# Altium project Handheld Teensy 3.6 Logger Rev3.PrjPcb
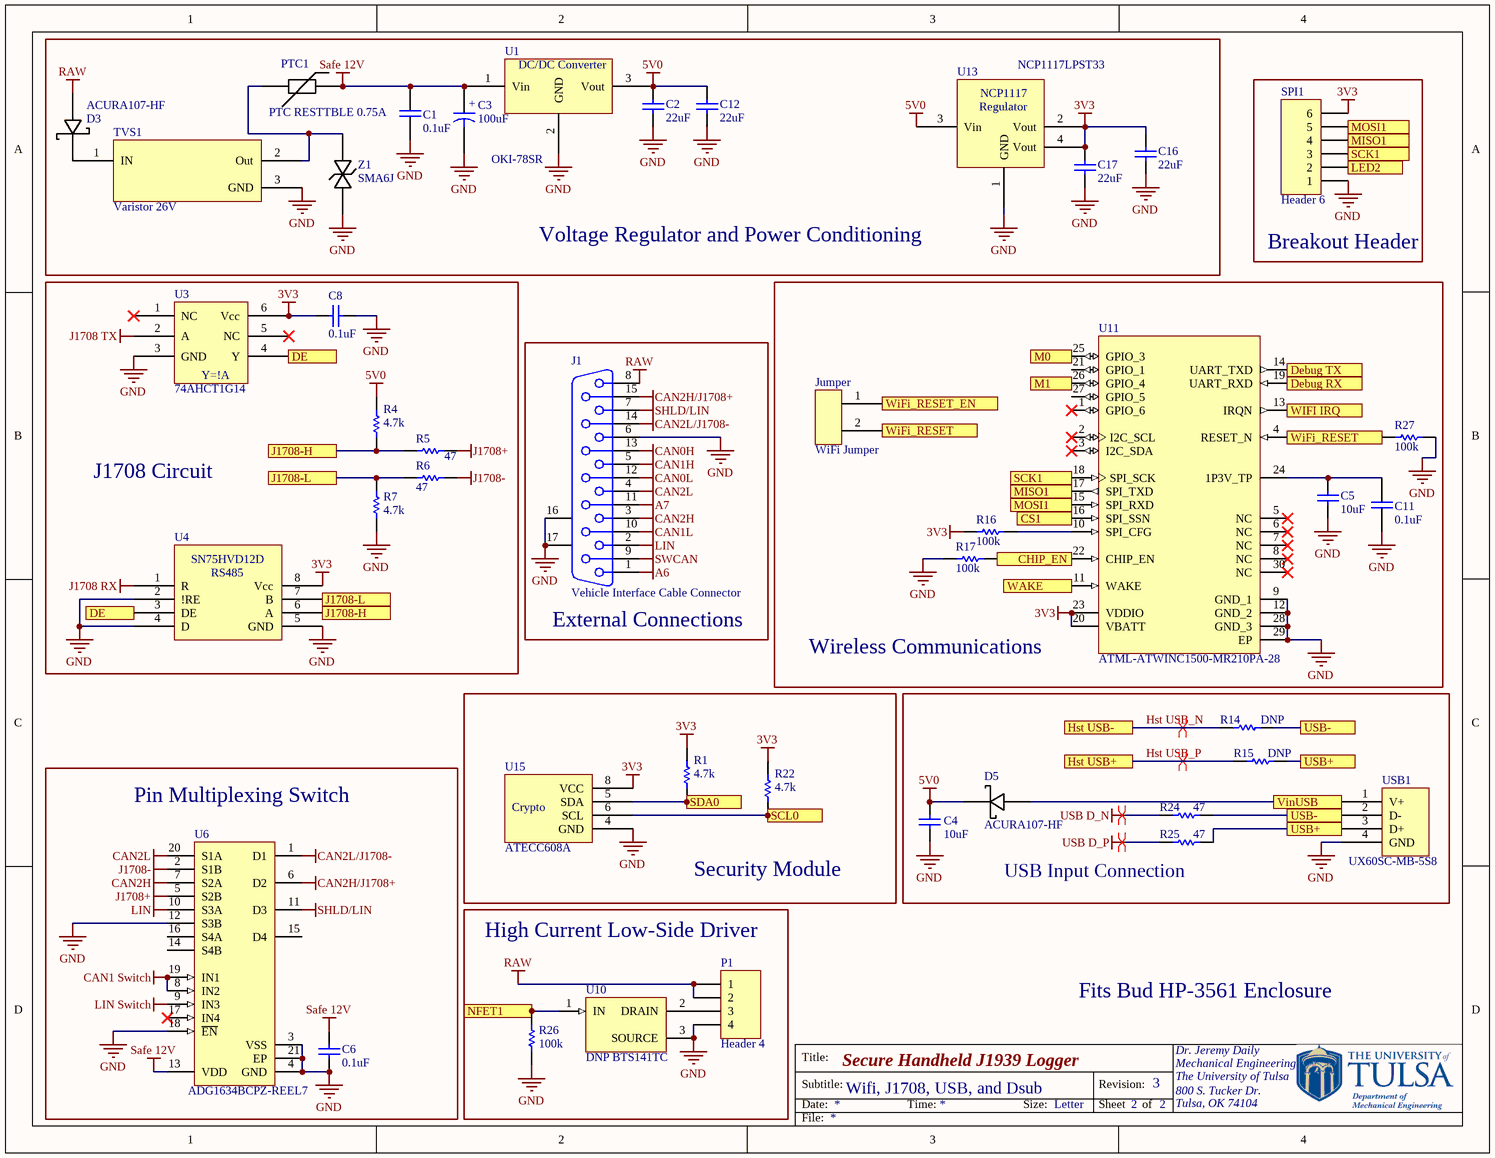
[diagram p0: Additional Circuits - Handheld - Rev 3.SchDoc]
2 sheets, 84 parts. Net scope: flat (ports and power ports of the same name join across sheets).
Board file: HP3561 PCB.PcbDoc
Sheets:
  Additional Circuits - Handheld - Rev 3.SchDoc
  Teensy 3.6 with J1939 - Handheld Rev3.SchDoc

## Sheet Additional Circuits - Handheld - Rev 3.SchDoc: Secure Handheld J1939 Logger
size Letter; Author: Dr. Jeremy Daily; CompanyName: The University of Tulsa; Organization: Mechanical Engineering; Address1: 800 S. Tucker Dr.; Address2: Tulsa, OK 74104; DocumentNumber: Wifi, J1708, USB, and Dsub; Revision: 3; SheetNumber: 2; SheetTotal: 2

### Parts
C1  0.1uF  [0603]
C2  22uF  [1206]
C3  100uF  [Elec. Cap - G]
C4  10uF  [0603]
C5  10uF  [0603]
C6  0.1uF  [0603]
C8  0.1uF  [0603]
C11  0.1uF  [0603]
C12  22uF  [1206]
C16  22uF  [1206]
C17  22uF  [1206]
D3  ACURA107-HF  [SMA with A and K]
D5  ACURA107-HF  [SMA with A and K]
J1  Vehicle Interface Cable Connector  [DSUB1.385-2H15]
Jumper  WiFi Jumper  [WiFi Jumper]
P1  Header 4  [HDR1X4]
PTC1  PTC RESTTBLE 0.75A  [1812]
R1  4.7k  [0603]
R4  4.7k  [0603]
R5  47  [0603]
R6  47  [0603]
R7  4.7k  [0603]
R14  DNP  [0603]
R15  DNP  [0603]
R16  100k  [0603]
R17  100k  [0603]
R22  4.7k  [0603]
R24  47  [0603]
R25  47  [0603]
R26  100k  [0603]
R27  100k  [0603]
SPI1  Header 6  [HDR1X6]
TVS1  Varistor 26V  [Transfeed]
U1  OKI-78SR  [OKI-78SR]
U3  74AHCT1G14  [SOT-353]
U4  SN75HVD08DR  [SOIC-SN8_N]  (value not drawn)
U6  ADG1634BCPZ-REEL7  [ADI-CP-20-4_N]
U10  DNP BTS141TC  [INF-PG-TO263-3-2_N]
U11  ATML-ATWINC1500-MR210PA-28  [ATML-ATWINC1500-MR210PA-28_V]
U13  NCP1117LPST33  [SOT-223]
U15  ATECC608A  [SOIC-8]
USB1  UX60SC-MB-5S8  [USB Mini UX60S]
Z1  SMA6J  [SMA]

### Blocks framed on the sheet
Voltage Regulator and Power Conditioning: C1-C3 C12 C16 C17 D3 PTC1 TVS1 U1 U13 Z1
Breakout Header: SPI1
J1708 Circuit: C8 R4-R7 U3 U4
Wireless Communications: C5 C11 Jumper R16 R17 R27 U11
External Connections: J1
Security Module: R1 R22 U15
USB Input Connection: C4 D5 R14 R15 R24 R25 USB1
Pin Multiplexing Switch: C6 U6
High Current Low-Side Driver: P1 R26 U10

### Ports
CHIP_EN, CS1, DE, Debug RX, Debug TX, Hst USB+, Hst USB-, J1708-H, J1708-L, LED2, M0, M1, MISO1, MOSI1, NFET1, SCK1, SCL0, SDA0, USB+, USB-, VinUSB, WAKE, WIFI IRQ, WiFi_RESET, WiFi_RESET_EN

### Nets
3V3: C8.2 C16.2 C17.2 R1.1 R16.2 R22.1 SPI1.6 U3.6(Vcc) U4.8(Vcc) U11.20(VBATT) U11.23(VDDIO) U13.2(Vout) U13.4(Vout) U15.8(VCC)
5V0: C2.2 C4.1 C12.2 D5.2(K) R4.1 U1.3(Vout) U13.3(Vin)
A6: J1.1
A7: J1.11
CAN0H: J1.13
CAN0L: J1.12
CAN1 Switch: U6.8(IN2) U6.19(IN1)
CAN1H: J1.5
CAN1L: J1.10
CAN2H: J1.3 U6.7(S2A)
CAN2H/J1708+: J1.15 U6.6(D2)
CAN2L: J1.4 U6.20(S1A)
CAN2L/J1708-: J1.14 U6.1(D1)
GND: C1.1 C2.1 C3.2(-) C4.2 C5.1 C6.1 C8.1 C11.1 C12.1 C16.1 C17.1 J1.6 J1.16(MH1) J1.17(MH2) P1.4 R7.2 R17.2 R26.2 R27.1 SPI1.1 TVS1.3(GND) U1.2(GND) U3.3(GND) U4.2(!RE) U4.4(D) U4.5(GND) U6.3(VSS) U6.4(GND) U6.12(S3B) U6.18(~{EN}) U6.21(EP) U10.3(SOURCE) U11.9(GND_1) U11.12(GND_2) U11.28(GND_3) U11.29(EP) U13.1(GND) U15.4(GND) USB1.4(GND) Z1.1(A)
J1708 RX: U4.1(R)
J1708 TX: U3.2(A)
J1708+: R5.2 U6.5(S2B)
J1708-: R6.2 U6.2(S1B)
LIN: J1.2 U6.10(S3A)
LIN Switch: U6.9(IN3)
RAW: D3.1(A) J1.8 P1.1 P1.2
Safe 12V: C1.2 C3.1 C6.2 PTC1.2 U1.1(Vin) U6.13(VDD)
SHLD/LIN: J1.7 U6.11(D3)
SWCAN: J1.9
USB D_N: R24.1
USB D_P: R25.1
Hst USB_N: R14.1 ; port Hst USB-
Hst USB_P: R15.1 ; port Hst USB+
NetC5_2: C5.2 C11.2 U11.24(1P3V_TP)
NetD2_1: SPI1.2 ; port LED2
NetD3_2: D3.2(K) TVS1.1(IN)
NetD5_1: D5.1(A) USB1.1(V+) ; port VinUSB
NetI2C_2: R22.2 U15.6(SCL) ; port SCL0
NetI2C_3: R1.2 U15.5(SDA) ; port SDA0
NetJumper_1: Jumper.1 ; port WiFi_RESET_EN
NetJumper_2: Jumper.2 R27.2 U11.4(RESET_N) ; port WiFi_RESET
NetP1_3: P1.3 U10.2(DRAIN)
NetPTC1_1: PTC1.1 TVS1.2(Out) Z1.2(K)
NetR4_2: R4.2 R5.1 U4.6(A) ; port J1708-H
NetR6_1: R6.1 R7.1 U4.7(B) ; port J1708-L
NetR14_2: R14.2 R24.2 USB1.2(D-) ; port USB-
NetR15_2: R15.2 R25.2 USB1.3(D+) ; port USB+
NetR16_1: R16.1 U11.10(SPI_CFG)
NetR17_1: R17.1 U11.22(CHIP_EN) ; port CHIP_EN
NetR26_1: R26.1 U10.1(IN) ; port NFET1
NetSPI1_3: SPI1.3 U11.18(SPI_SCK) ; port SCK1
NetSPI1_4: SPI1.4 U11.17(SPI_TXD) ; port MISO1
NetSPI1_5: SPI1.5 U11.15(SPI_RXD) ; port MOSI1
NetTeensy_3.6_30: U11.13(IRQN) ; port WIFI IRQ
NetTeensy_3.6_45: U11.16(SPI_SSN) ; port CS1
NetTeensy_3.6_63: U11.11(WAKE) ; port WAKE
NetTeensy_3.6_72: U11.19(UART_RXD) ; port Debug RX
NetTeensy_3.6_74: U11.14(UART_TXD) ; port Debug TX
NetU2_2: U11.25(GPIO_3) ; port M0
NetU2_3: U11.26(GPIO_4) ; port M1
NetU3_4: U3.4(Y) U4.3(DE) ; port DE

Not connected (* = marked no-connect by the designer): U3 1(NC)* 5(NC)*; U6 14(S4B) 15(D4) 16(S4A) 17(IN4)*; U11 1(GPIO_6)* 2(I2C_SCL)* 3(I2C_SDA)* 5(NC)* 6(NC)* 7(NC)* 8(NC)* 21(GPIO_1) 27(GPIO_5) 30(NC)*

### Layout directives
differential pair: Hst USB_N, Hst USB_P, USB D_N, USB D_P

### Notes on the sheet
- Fits Bud HP-3561 Enclosure

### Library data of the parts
C1 C11 = Cap: CAP CER 0.1UF 50V X7R 0603; Manufacturer: KEMET; PartNumber: C0603C104K5RACAUTO
C2 C12 C16 C17 = Cap: 22µF ±20% 25V Ceramic Capacitor X5R 1206 (3216 Metric); Manufacturer: Murata Electronics North America; PartNumber: GRT31CR61E226ME01L
C3 = Tantalum Cap_1: Aluminum Electrolytic Capacitors Radial, Can - SMD 5000 Hrs @ 105°C; Manufacturer: Panasonic Electronic Components; PartNumber: EEE-HC1H101P
C4 C5 = Cap: 10µF ±20% 25V Ceramic Capacitor X5R 0603 (1608 Metric); Manufacturer: Murata Electronics North America; PartNumber: ZRB18AR61E106ME01L
C6 C8 = Cap: CAP CER 0.1UF 50V 10% X7R 0603; Manufacturer: KEMET; PartNumber: C0603C104K5RACAUTO
D3 D5 = Schottky Diode: Diode Schottky 1000V 1A Surface Mount DO-214AC (SMA); Manufacturer: Comchip Technology
J1 = D Connector 15: Receptacle Assembly, 15 Position, Right Angle; Manufacturer: Amphenol FCI; PartNumber: D15S33E4GV00LF
P1 = Header 4: Header, 4-Pin
PTC1 = PTC: PTC RESTTBLE 0.75A 33V CHIP 1812; Manufacturer: Bel Fuse Inc.; PartNumber: 0ZCG0075BF2B
R1 R4 R7 R22 = Chip Resistor: ±1% 0.1W, 1/10W Chip Resistor 0603 (1608 Metric) Automotive AEC-Q200, High Voltage Thick Film; Manufacturer: Rohm Semiconductor; PartNumber: KTR03EZPF4701
R5 R6 R24 R25 = Chip Resistor: ±1% 0.1W, 1/10W Chip Resistor 0603 (1608 Metric) Automotive AEC-Q200, High Voltage Thick Film; Manufacturer: Rohm Semiconductor; PartNumber: KTR03EZPF47R0
R14 R15 = Chip Resistor: RES SMD 47 OHM 1% 1/10W 0603; Manufacturer: Panasonic Electronic Components; PartNumber: ERJ-3EKF47R0V
R16 R17 R26 R27 = Chip Resistor: ±1% 0.1W, 1/10W Chip Resistor 0603 (1608 Metric) Automotive AEC-Q200, High Voltage Thick Film; Manufacturer: Rohm Semiconductor; PartNumber: KTR03EZPF1003
SPI1 = Header 6: Header, 6-Pin
TVS1 = Transfeed: 34.5V 80A Varistor 1 Circuit Surface Mount 0805 (2012 Metric); Manufacturer: AVX; PartNumber: V2AF126C600Y2EDP
U1 = 7805: 5V DC/DC Converter (7805 replacement); Manufacturer: Murata Power Solutions Inc.; PartNumber: OKI-78SR-5/1.5-W36H-C
U3 = 74AHCT1G14 Inverter: IC SCHMIT-TRIGG INV GATE SOT353; Manufacturer: Diodes Incorporated; PartNumber: 74AHCT1G14SE-7
U4 = SN75HVD12D (3.3v RS485): IC RS485 TXRX 3/5V 8-SOIC; Manufacturer: Texas Instruments
U6 = ADG1634BCPZ-REEL7: IC SWITCH QUAD SPDT 20LFCSP; Manufacturer: Analog Devices
U10 = BTS141TC: Smart Low-Side Power Switch HITFET, 60 V VDS, 12 A ID, -40 to 150 degC, PG-TO263-3-2, Reel, Green; Manufacturer: Infineon; PartNumber: BTS141TCBUMA1
U11 = ATML-ATWINC1500-MR210PA-28: SMARTCONNECT ATWINC1500B-MU-T MO; Manufacturer: Microchip Technologies; PartNumber: ATWINC1510-MR210PB1140
U13 = NCP1117 2.5V: Linear Voltage Regulator IC Positive Fixed Output 3.3V 1A SOT-223; Manufacturer: On Semiconductor; PartNumber: NCP1117LPST33T3G
U15 = ATECC508A: Authentication Chip IC Networking and Communications 8-SOIC; Manufacturer: Microchip Technology; PartNumber: ATECC608A-SSHCZ-T
USB1 = USB-Rugged: USB - mini B USB 2.0 Receptacle Connector 5 Position Surface Mount, Right Angle; Through Hole; Manufacturer: Hirose
Z1 = Zener - Bidirectional: TVS DIODE 20VWM 36.8VC SMA; Manufacturer: Micro Commercial Co; PartNumber: SMA6J24CA-TP

## Sheet Teensy 3.6 with J1939 - Handheld Rev3.SchDoc: Secure Handheld J1939 Logger
size Letter; Author: Dr. Jeremy Daily; CompanyName: The University of Tulsa; Organization: Mechanical Engineering; Address1: 800 S. Tucker Dr.; Address2: Tulsa, OK 74104; DocumentNumber: Hands-On Heavy Duty Networking; Revision: 3; SheetNumber: 1; SheetTotal: 2
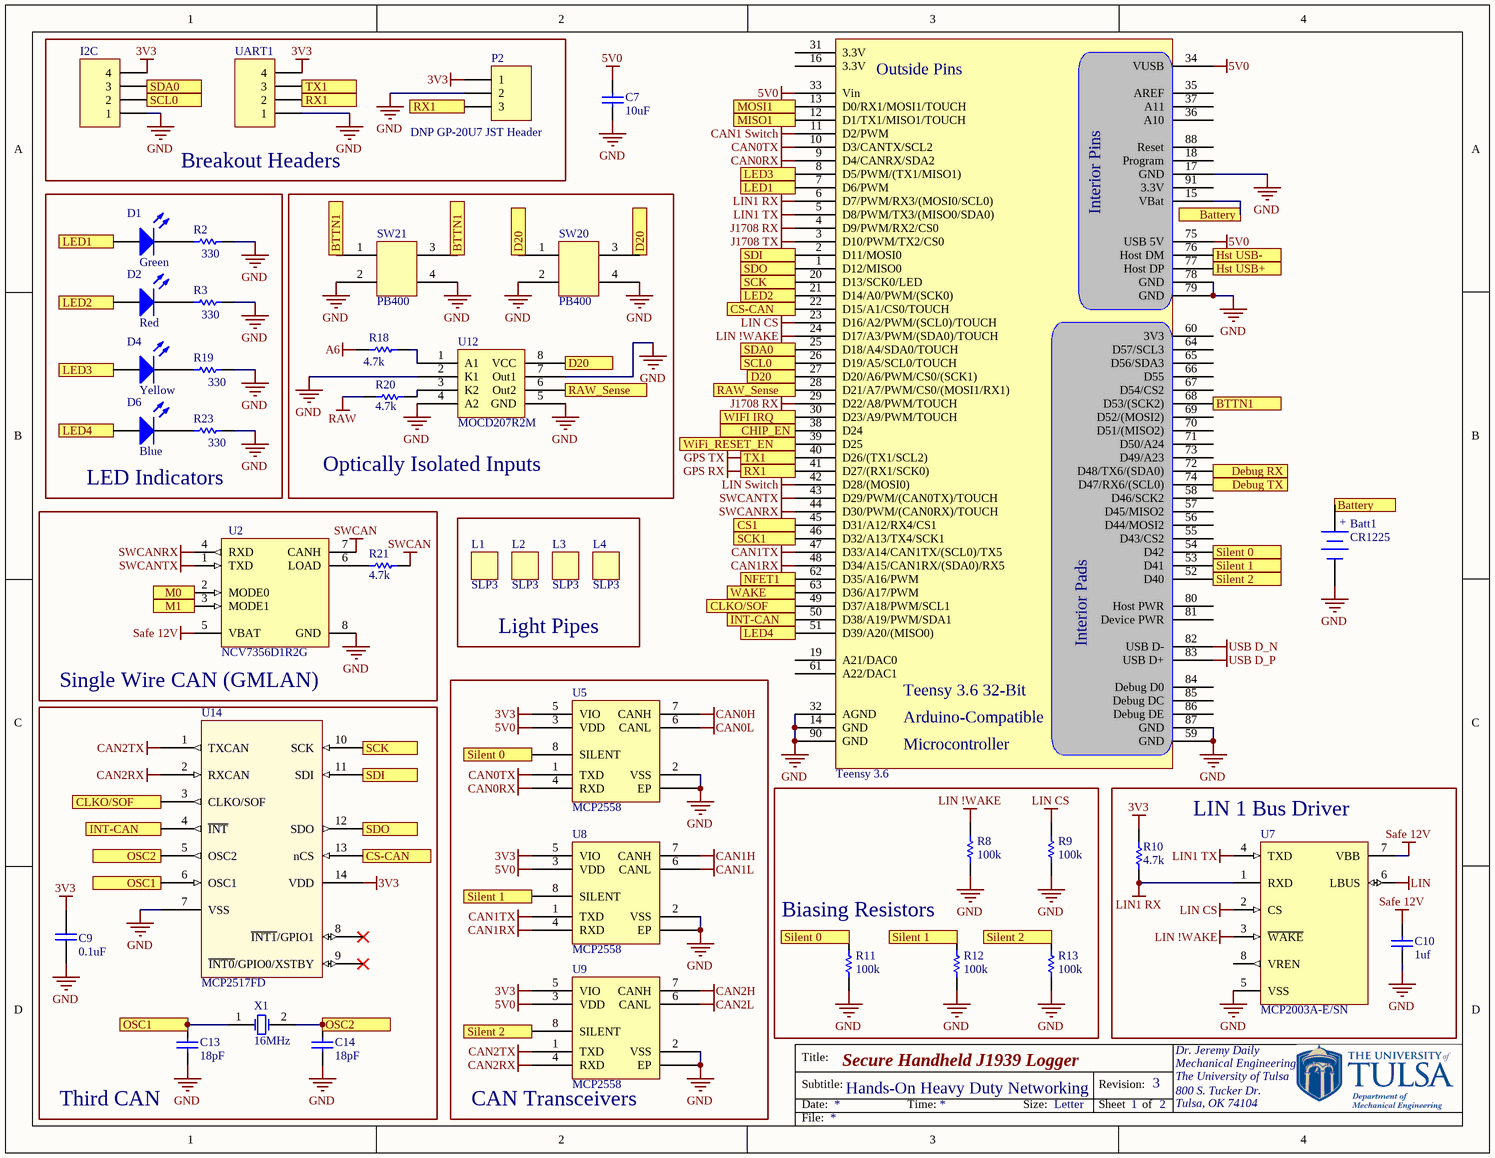
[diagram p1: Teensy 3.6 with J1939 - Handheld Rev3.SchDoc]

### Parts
Batt1  CR1225  [Battery Clip - CR1225]
C7  10uF  [0603]
C9  0.1uF  [0603]
C10  1uf  [0603]
C13  18pF  [0603]
C14  18pF  [0603]
D1  Green  [0805 Polarized]
D2  Red  [0805 Polarized]
D4  Yellow  [0805 Polarized]
D6  Blue  [0805 Polarized]
I2C  Header 4  [HDR1X4]  (value not drawn)
L1  SLP3  [PCBComponent_1]
L2  SLP3  [PCBComponent_1]
L3  SLP3  [PCBComponent_1]
L4  SLP3  [PCBComponent_1]
P2  DNP GP-20U7 JST Header  [MHDR1X3]
R2  330  [0603]
R3  330  [0603]
R8  100k  [0603]
R9  100k  [0603]
R10  4.7k  [0603]
R11  100k  [0603]
R12  100k  [0603]
R13  100k  [0603]
R18  4.7k  [0603]
R19  330  [0603]
R20  4.7k  [0603]
R21  4.7k  [0603]
R23  330  [0603]
SW20  PB400  [PB400]
SW21  PB400  [PB400]
Teensy_3.6  Teensy 3.6  [Teensy 3.6 Surface Mount]  (value not drawn)
U2  NCV7356D1R2G  [ONSC-SOIC-8-751-07_V]
U5  MCP2558  [TDFN]
U7  MCP2003A-E/SN  [SOIC-SN8_N]
U8  MCP2558  [TDFN]
U9  MCP2558  [TDFN]
U12  MOCD207R2M  [SOIC-8]
U14  MCP2517FD  [SOP14]
UART1  Header 4  [HDR1X4]  (value not drawn)
X1  16MHz  [XTAL 2 pad]

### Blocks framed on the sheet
Breakout Headers: I2C P2 UART1
LED Indicators: D1 D2 D4 D6 R2 R3 R19 R23
Optically Isolated Inputs: R18 R20 SW20 SW21 U12
Single Wire CAN (GMLAN): R21 U2
Light Pipes: L1-L4
CAN Transceivers: U5 U8 U9
Third CAN: C9 C13 C14 U14 X1
Biasing Resistors: R8 R9 R11-R13
LIN 1 Bus Driver: C10 R10 U7

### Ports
Battery, BTTN1, CHIP_EN, CLKO/SOF, CS1, CS-CAN, D20, Debug RX, Debug TX, Hst USB+, Hst USB-, INT-CAN, LED1, LED2, LED3, LED4, M0, M1, MISO1, MOSI1, NFET1, OSC1, OSC2, RAW_Sense, RX1, SCK, SCK1, SCL0, SDA0, SDI, SDO, Silent 0, Silent 1, Silent 2, TX1, WAKE, WIFI IRQ, WiFi_RESET_EN

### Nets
3V3: C9.2 I2C.4 P2.1 R10.2 U5.5(VIO) U8.5(VIO) U9.5(VIO) U14.14(VDD) UART1.4
5V0: C7.1 Teensy_3.6.33(Vin) Teensy_3.6.34(VUSB) Teensy_3.6.75(USB_5V) U5.3(VDD) U8.3(VDD) U9.3(VDD)
A6: R18.1
CAN0H: U5.7(CANH)
CAN0L: U5.6(CANL)
CAN0RX: Teensy_3.6.9(D4/CANRX/SDA2) U5.4(RXD)
CAN0TX: Teensy_3.6.10(D3/CANTX/SCL2) U5.1(TXD)
CAN1 Switch: Teensy_3.6.11(D2/PWM)
CAN1H: U8.7(CANH)
CAN1L: U8.6(CANL)
CAN1RX: Teensy_3.6.48(D34/A15/CAN1RX/(SDA0)/RX5) U8.4(RXD)
CAN1TX: Teensy_3.6.47(D33/A14/CAN1TX/(SCL0)/TX5) U8.1(TXD)
CAN2H: U9.7(CANH)
CAN2L: U9.6(CANL)
CAN2RX: U9.4(RXD) U14.2(RXCAN)
CAN2TX: U9.1(TXD) U14.1(TXCAN)
GND: Batt1.2(-) C7.2 C9.1 C10.2 C13.1 C14.1 I2C.1 P2.2 R2.2 R3.2 R8.2 R9.2 R11.2 R12.2 R13.2 R19.2 R23.2 SW20.2 SW20.4 SW21.2 SW21.4 Teensy_3.6.14(GND) Teensy_3.6.17(GND) Teensy_3.6.32(AGND) Teensy_3.6.59(GND) Teensy_3.6.78(GND) Teensy_3.6.79(GND) Teensy_3.6.87(GND) Teensy_3.6.90(GND) U2.8(GND) U5.0(EP) U5.2(VSS) U7.5(VSS) U8.0(EP) U8.2(VSS) U9.0(EP) U9.2(VSS) U12.2(K1) U12.4(A2) U12.5(GND) U12.7(Out1) U14.7(VSS) UART1.1
GPS RX: P2.3 Teensy_3.6.41(D27/(RX1/SCK0)) UART1.2 ; port RX1
GPS TX: Teensy_3.6.40(D26/(TX1/SCL2)) UART1.3 ; port TX1
J1708 RX: Teensy_3.6.4(D9/PWM/RX2/CS0) Teensy_3.6.29(D22/A8/PWM/TOUCH)
J1708 TX: Teensy_3.6.3(D10/PWM/TX2/CS0)
LIN: U7.6(LBUS)
LIN1 RX: R10.1 Teensy_3.6.6(D7/PWM/RX3/(MOSI0/SCL0)) U7.1(RXD)
LIN1 TX: Teensy_3.6.5(D8/PWM/TX3/(MISO0/SDA0)) U7.4(TXD)
LIN !WAKE: R8.1 Teensy_3.6.24(D17/A3/PWM/(SDA0)/TOUCH) U7.3(~{WAKE})
LIN CS: R9.1 Teensy_3.6.23(D16/A2/PWM/(SCL0)/TOUCH) U7.2(CS)
LIN Switch: Teensy_3.6.42(D28/(MOSI0))
RAW: R20.1
Safe 12V: C10.1 U2.5(VBAT) U7.7(VBB)
SWCAN: R21.2 U2.7(CANH)
SWCANRX: Teensy_3.6.44(D30/PWM/(CAN0RX)/TOUCH) U2.4(RXD)
SWCANTX: Teensy_3.6.43(D29/PWM/(CAN0TX)/TOUCH) U2.1(TXD)
USB D_N: Teensy_3.6.82(USB_D-)
USB D_P: Teensy_3.6.83(USB_D+)
Hst USB_N: Teensy_3.6.76(Host_DM) ; port Hst USB-
Hst USB_P: Teensy_3.6.77(Host_DP) ; port Hst USB+
NetBatt1_1: Batt1.1(+) Teensy_3.6.15(VBat) ; port Battery
NetC13_2: C13.2 U14.6(OSC1) X1.1(OSC1) ; port OSC1
NetC14_2: C14.2 U14.5(OSC2) X1.2(OSC2) ; port OSC2
NetD1_1: D1.1(A) Teensy_3.6.7(D6/PWM) ; port LED1
NetD1_2: D1.2(K) R2.1
NetD2_1: D2.1(A) Teensy_3.6.21(D14/A0/PWM/(SCK0)) ; port LED2
NetD2_2: D2.2(K) R3.1
NetD4_1: D4.1(A) Teensy_3.6.8(D5/PWM/(TX1/MISO1)) ; port LED3
NetD4_2: D4.2(K) R19.1
NetD6_1: D6.1(A) Teensy_3.6.51(D39/A20/(MISO0)) ; port LED4
NetD6_2: D6.2(K) R23.1
NetI2C_2: I2C.2 Teensy_3.6.26(D19/A5/SCL0/TOUCH) ; port SCL0
NetI2C_3: I2C.3 Teensy_3.6.25(D18/A4/SDA0/TOUCH) ; port SDA0
NetJumper_1: Teensy_3.6.39(D25) ; port WiFi_RESET_EN
NetR11_1: R11.1 Teensy_3.6.54(D42) U5.8(SILENT) ; port Silent 0
NetR12_1: R12.1 Teensy_3.6.53(D41) U8.8(SILENT) ; port Silent 1
NetR13_1: R13.1 Teensy_3.6.52(D40) U9.8(SILENT) ; port Silent 2
NetR17_1: Teensy_3.6.38(D24) ; port CHIP_EN
NetR18_2: R18.2 U12.1(A1)
NetR20_2: R20.2 U12.3(K2)
NetR21_1: R21.1 U2.6(LOAD)
NetR26_1: Teensy_3.6.62(D35/A16/PWM) ; port NFET1
NetSPI1_3: Teensy_3.6.46(D32/A13/TX4/SCK1) ; port SCK1
NetSPI1_4: Teensy_3.6.12(D1/TX1/MISO1/TOUCH) ; port MISO1
NetSPI1_5: Teensy_3.6.13(D0/RX1/MOSI1/TOUCH) ; port MOSI1
NetSW20_1: SW20.1 SW20.3 Teensy_3.6.27(D20/A6/PWM/CS0/(SCK1)) U12.8(VCC) ; port D20
NetSW21_1: SW21.1 SW21.3 Teensy_3.6.68(D53/(SCK2)) ; port BTTN1
NetTeensy_3.6_1: Teensy_3.6.1(D12/MISO0) U14.12(SDO) ; port SDO
NetTeensy_3.6_2: Teensy_3.6.2(D11/MOSI0) U14.11(SDI) ; port SDI
NetTeensy_3.6_20: Teensy_3.6.20(D13/SCK0/LED) U14.10(SCK) ; port SCK
NetTeensy_3.6_22: Teensy_3.6.22(D15/A1/CS0/TOUCH) U14.13(nCS) ; port CS-CAN
NetTeensy_3.6_28: Teensy_3.6.28(D21/A7/PWM/CS0/(MOSI1/RX1)) U12.6(Out2) ; port RAW_Sense
NetTeensy_3.6_30: Teensy_3.6.30(D23/A9/PWM/TOUCH) ; port WIFI IRQ
NetTeensy_3.6_45: Teensy_3.6.45(D31/A12/RX4/CS1) ; port CS1
NetTeensy_3.6_49: Teensy_3.6.49(D37/A18/PWM/SCL1) U14.3(CLKO/SOF) ; port CLKO/SOF
NetTeensy_3.6_50: Teensy_3.6.50(D38/A19/PWM/SDA1) U14.4(~{INT}) ; port INT-CAN
NetTeensy_3.6_63: Teensy_3.6.63(D36/A17/PWM) ; port WAKE
NetTeensy_3.6_72: Teensy_3.6.72(D48/TX6/(SDA0)) ; port Debug RX
NetTeensy_3.6_74: Teensy_3.6.74(D47/RX6/(SCL0)) ; port Debug TX
NetU2_2: U2.2(MODE0) ; port M0
NetU2_3: U2.3(MODE1) ; port M1

Not connected (* = marked no-connect by the designer): Teensy_3.6 16(3.3V) 18(Program) 19(A21/DAC0) 31(3.3V) 35(AREF) 36(A10) 37(A11) 55(D43/CS2) 56(D44/MOSI2) 57(D45/MISO2) 58(D46/SCK2) 60(3V3) 61(A22/DAC1) 64(D57/SCL3) 65(D56/SDA3) 66(D55) 67(D54/CS2) 69(D52/(MOSI2)) 70(D51/(MISO2)) 71(D50/A24) 73(D49/A23) 80(Host_PWR) 81(Device_PWR) 84(Debug_D0) 85(Debug_DC) 86(Debug_DE) 88(Reset) 91(3.3V); U7 8(VREN); U14 8(~{INT1}/GPIO1)* 9(~{INT0}/GPIO0/XSTBY)*

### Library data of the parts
Batt1 = CR2032 Battery Holder: Lithium Battery Non-Rechargeable (Primary) 3V Coin, 12.5mm; Manufacturer: Linx; PartNumber: BAT-HLD-012-SMT
C7 = Cap: as C4 on sheet Additional Circuits - Handheld - Rev 3
C9 = Cap: as C1 on sheet Additional Circuits - Handheld - Rev 3
C10 = Cap: 1µF ±20% 50V Ceramic Capacitor X5R 0603 (1608 Metric); Manufacturer: Murata Electronics North America; PartNumber: GRT188R61H105ME13D
C13 C14 = Cap: 18pF ±5% 50V Ceramic Capacitor C0G, NP0 0603 (1608 Metric); Manufacturer: Kemet; PartNumber: C0603C180J5GACAUTO
D1 = LED - SMD: Green 570nm LED Indication - Discrete 2.2V 0805 (2012 Metric); Manufacturer: OSRAM Opto Semiconductors Inc.; PartNumber: LG R971-KN-1
D2 = LED - SMD: Red 633nm LED Indication - Discrete 2V 0805 (2012 Metric); Manufacturer: OSRAM Opto Semiconductors Inc.; PartNumber: LS R976-NR-1
D4 = LED - SMD: LED YELLOW DIFFUSED 0805 SMD; Manufacturer: OSRAM Opto Semiconductors Inc.; PartNumber: LY R976-PS-36
D6 = LED - SMD: Blue 470nm LED Indication - Discrete 3.3V 0805 (2012 Metric); Manufacturer: Broadcom Limited; PartNumber: HSMN-C170
I2C UART1 = Header 4: Header, 4-Pin
L1-L4 = SLP3: Manufacturer: Bivar Inc.; PartNumber: SLP3-150-250-R
P2 = MHDR1X3: CONN HEADER PH SIDE 3POS 2MM SMD; PartNumber: S3B-PH-SM4-TB(LF)(SN)
R2 R3 R19 R23 = Chip Resistor: 330 Ohms ±1% 0.1W, 1/10W Chip Resistor 0603 (1608 Metric) Automotive AEC-Q200, High Voltage Thick Film; Manufacturer: Rohm Semiconductor; PartNumber: KTR03EZPF3300
R8 R9 R11-R13 = Chip Resistor: as R16 on sheet Additional Circuits - Handheld - Rev 3
R10 R18 R20 R21 = Chip Resistor: as R1 on sheet Additional Circuits - Handheld - Rev 3
SW20 SW21 = PB400: Pushbutton Switch DPST-NO Standard Through Hole, Right Angle; Manufacturer: E-Switch; PartNumber: PB400OAQR1BLK
Teensy_3.6 = Teensy 3.6: K66 Teensy 3.6 Kinetis MCU 32-Bit ARM® Cortex®-M4 Embedded Evaluation Board; Manufacturer: PRJC
U2 = NCV7356D1G: Single Wire CAN Transceiver, 5 to 27 V, 8-Pin SOIC, Pb-Free, Tube; Manufacturer: On Semiconductor
U5 = MCP2558FD: Microchip CAN FD Transceiver with Silent Mode; Manufacturer: Microchip Technology; PartNumber: MCP2558FDT-H/MNY
U7 = MCP2003AT-E/SN: LIN J2602 Transceiver, 8-Pin SOIC, Extended Temperature, Tape and Reel; Manufacturer: Microchip Technology
U8 U9 = MCP2558FD: Microchip CAN FD Transceiver with Silent Mode; PartNumber: MCP2558FDT-H/MNY
U12 = Optoisolator - Dual: Optoisolator Transistor Output 2500Vrms 2 Channel 8-SO Tall; Manufacturer: Fairchild/ON Semiconductor
U14 = MCP2517FD: CANbus Controller CAN 2.0 SPI Interface 14-VDFN (4.5x3); Manufacturer: Microchip Technology; PartNumber: MCP2517FDT-H/JHA
X1 = Crystal Oscillator: CRYSTAL 16MHZ 18PF SMD; Manufacturer: TXC CORPORATION; PartNumber: 7A-16.000MAAJ-T

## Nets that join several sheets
3V3: Additional Circuits - Handheld - Rev 3 (14 pins), Teensy 3.6 with J1939 - Handheld Rev3 (9 pins)
5V0: Additional Circuits - Handheld - Rev 3 (7 pins), Teensy 3.6 with J1939 - Handheld Rev3 (7 pins)
A6: Additional Circuits - Handheld - Rev 3 (J1.1), Teensy 3.6 with J1939 - Handheld Rev3 (R18.1)
CAN0H: Additional Circuits - Handheld - Rev 3 (J1.13), Teensy 3.6 with J1939 - Handheld Rev3 (U5.7)
CAN0L: Additional Circuits - Handheld - Rev 3 (J1.12), Teensy 3.6 with J1939 - Handheld Rev3 (U5.6)
CAN1 Switch: Additional Circuits - Handheld - Rev 3 (U6.8 U6.19), Teensy 3.6 with J1939 - Handheld Rev3 (Teensy_3.6.11)
CAN1H: Additional Circuits - Handheld - Rev 3 (J1.5), Teensy 3.6 with J1939 - Handheld Rev3 (U8.7)
CAN1L: Additional Circuits - Handheld - Rev 3 (J1.10), Teensy 3.6 with J1939 - Handheld Rev3 (U8.6)
CAN2H: Additional Circuits - Handheld - Rev 3 (J1.3 U6.7), Teensy 3.6 with J1939 - Handheld Rev3 (U9.7)
CAN2L: Additional Circuits - Handheld - Rev 3 (J1.4 U6.20), Teensy 3.6 with J1939 - Handheld Rev3 (U9.6)
GND: Additional Circuits - Handheld - Rev 3 (40 pins), Teensy 3.6 with J1939 - Handheld Rev3 (43 pins)
J1708 RX: Additional Circuits - Handheld - Rev 3 (U4.1), Teensy 3.6 with J1939 - Handheld Rev3 (Teensy_3.6.4 Teensy_3.6.29)
J1708 TX: Additional Circuits - Handheld - Rev 3 (U3.2), Teensy 3.6 with J1939 - Handheld Rev3 (Teensy_3.6.3)
LIN: Additional Circuits - Handheld - Rev 3 (J1.2 U6.10), Teensy 3.6 with J1939 - Handheld Rev3 (U7.6)
LIN Switch: Additional Circuits - Handheld - Rev 3 (U6.9), Teensy 3.6 with J1939 - Handheld Rev3 (Teensy_3.6.42)
RAW: Additional Circuits - Handheld - Rev 3 (D3.1 J1.8 P1.1 P1.2), Teensy 3.6 with J1939 - Handheld Rev3 (R20.1)
Safe 12V: Additional Circuits - Handheld - Rev 3 (6 pins), Teensy 3.6 with J1939 - Handheld Rev3 (C10.1 U2.5 U7.7)
SWCAN: Additional Circuits - Handheld - Rev 3 (J1.9), Teensy 3.6 with J1939 - Handheld Rev3 (R21.2 U2.7)
USB D_N: Additional Circuits - Handheld - Rev 3 (R24.1), Teensy 3.6 with J1939 - Handheld Rev3 (Teensy_3.6.82)
USB D_P: Additional Circuits - Handheld - Rev 3 (R25.1), Teensy 3.6 with J1939 - Handheld Rev3 (Teensy_3.6.83)
Hst USB_N: Additional Circuits - Handheld - Rev 3 (R14.1), Teensy 3.6 with J1939 - Handheld Rev3 (Teensy_3.6.76)
Hst USB_P: Additional Circuits - Handheld - Rev 3 (R15.1), Teensy 3.6 with J1939 - Handheld Rev3 (Teensy_3.6.77)
NetD2_1: Additional Circuits - Handheld - Rev 3 (SPI1.2), Teensy 3.6 with J1939 - Handheld Rev3 (D2.1 Teensy_3.6.21)
NetI2C_2: Additional Circuits - Handheld - Rev 3 (R22.2 U15.6), Teensy 3.6 with J1939 - Handheld Rev3 (I2C.2 Teensy_3.6.26)
NetI2C_3: Additional Circuits - Handheld - Rev 3 (R1.2 U15.5), Teensy 3.6 with J1939 - Handheld Rev3 (I2C.3 Teensy_3.6.25)
NetJumper_1: Additional Circuits - Handheld - Rev 3 (Jumper.1), Teensy 3.6 with J1939 - Handheld Rev3 (Teensy_3.6.39)
NetR17_1: Additional Circuits - Handheld - Rev 3 (R17.1 U11.22), Teensy 3.6 with J1939 - Handheld Rev3 (Teensy_3.6.38)
NetR26_1: Additional Circuits - Handheld - Rev 3 (R26.1 U10.1), Teensy 3.6 with J1939 - Handheld Rev3 (Teensy_3.6.62)
NetSPI1_3: Additional Circuits - Handheld - Rev 3 (SPI1.3 U11.18), Teensy 3.6 with J1939 - Handheld Rev3 (Teensy_3.6.46)
NetSPI1_4: Additional Circuits - Handheld - Rev 3 (SPI1.4 U11.17), Teensy 3.6 with J1939 - Handheld Rev3 (Teensy_3.6.12)
NetSPI1_5: Additional Circuits - Handheld - Rev 3 (SPI1.5 U11.15), Teensy 3.6 with J1939 - Handheld Rev3 (Teensy_3.6.13)
NetTeensy_3.6_30: Additional Circuits - Handheld - Rev 3 (U11.13), Teensy 3.6 with J1939 - Handheld Rev3 (Teensy_3.6.30)
NetTeensy_3.6_45: Additional Circuits - Handheld - Rev 3 (U11.16), Teensy 3.6 with J1939 - Handheld Rev3 (Teensy_3.6.45)
NetTeensy_3.6_63: Additional Circuits - Handheld - Rev 3 (U11.11), Teensy 3.6 with J1939 - Handheld Rev3 (Teensy_3.6.63)
NetTeensy_3.6_72: Additional Circuits - Handheld - Rev 3 (U11.19), Teensy 3.6 with J1939 - Handheld Rev3 (Teensy_3.6.72)
NetTeensy_3.6_74: Additional Circuits - Handheld - Rev 3 (U11.14), Teensy 3.6 with J1939 - Handheld Rev3 (Teensy_3.6.74)
NetU2_2: Additional Circuits - Handheld - Rev 3 (U11.25), Teensy 3.6 with J1939 - Handheld Rev3 (U2.2)
NetU2_3: Additional Circuits - Handheld - Rev 3 (U11.26), Teensy 3.6 with J1939 - Handheld Rev3 (U2.3)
